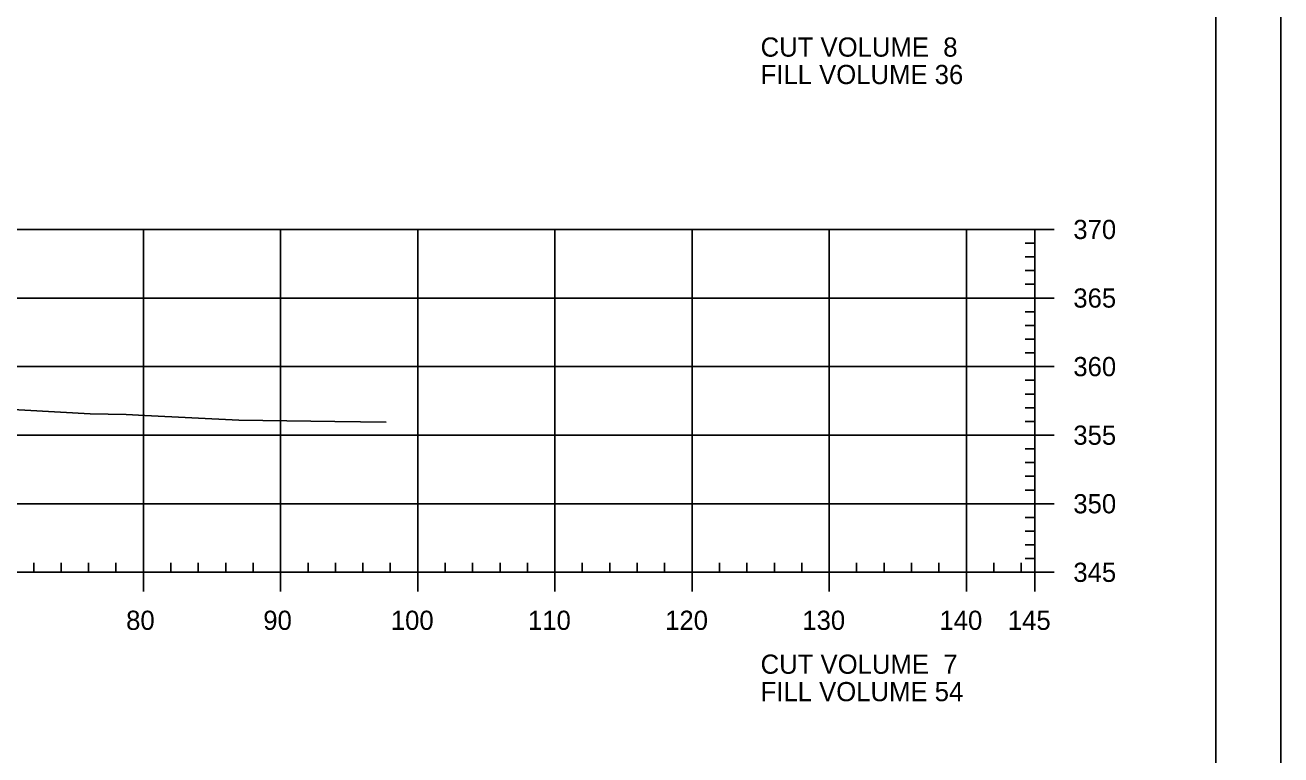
# Model space of a CAD drawing. Extents: x 1359801 to 1362404, y 372415 to 374228.
# Drawn here: x 1360042.7 to 1360134.3, y 373054.6 to 373107.8 of the extents above; entities that cross this region are included whole.
import ezdxf

# ---------------------------------------------------------------- set-up
doc = ezdxf.new("R2010")
doc.units = 0
for name, color, linetype in [('S_DRG_PT_SYM', 7, 'Continuous'), ('S_MAILBOX', 7, 'Continuous'), ('S_PRIMARY_CTL', 7, 'Continuous'), ('S_SHOULDER', 7, 'Continuous'), ('S_UTL_PT_SYM', 7, 'Continuous'), ('S_WATER_UTILITIES', 7, 'Continuous')]:
    doc.layers.add(name, color=color, linetype=linetype)

msp = doc.modelspace()

# ---------------------------------------------------------------- linework, layer by layer
at = {"layer": 'S_DRG_PT_SYM'}
msp.add_lwpolyline([(1360034.888, 373080.172), (1360047.473, 373079.465), (1360050.094, 373079.434), (1360051.445, 373079.352), (1360058.295, 373079.018), (1360065.315, 373078.917), (1360069.058, 373078.872)], dxfattribs=at)
at = {"layer": 'S_MAILBOX'}
for p, q in [((1359826.35, 373092.922), (1360116.35, 373092.922)), ((1360051.35, 373067.922), (1360051.35, 373092.922)), ((1360061.35, 373067.922), (1360061.35, 373092.922)), ((1360071.35, 373067.922), (1360071.35, 373092.922)), ((1360081.35, 373067.922), (1360081.35, 373092.922)), ((1360091.35, 373067.922), (1360091.35, 373092.922)), ((1360101.35, 373067.922), (1360101.35, 373092.922)), ((1360111.35, 373067.922), (1360111.35, 373092.922)), ((1360116.35, 373067.922), (1360116.35, 373092.922)), ((1359826.35, 373087.922), (1360116.35, 373087.922)), ((1359826.35, 373082.922), (1360116.35, 373082.922)), ((1359826.35, 373077.922), (1360116.35, 373077.922)), ((1359826.35, 373072.922), (1360116.35, 373072.922)), ((1359826.35, 373067.922), (1360116.35, 373067.922))]:
    msp.add_line(p, q, dxfattribs=at)
at = {"layer": 'S_SHOULDER'}
for points in [[(1359800.943, 373161.276), (1360134.283, 373161.276), (1360134.283, 372947.939), (1359800.943, 372947.939)], [(1360047.27, 373157.382), (1360047.27, 373147.502), (1360083.002, 373147.502), (1360083.002, 373144.582), (1360106.202, 373144.582), (1360106.202, 373120.249), (1360129.53, 373120.249), (1360129.53, 372951.922), (1359813.35, 372951.922), (1359813.35, 373157.382)]]:
    msp.add_lwpolyline(points, close=True, dxfattribs=at)
at = {"layer": 'S_UTL_PT_SYM'}
msp.add_line((1360129.53, 372951.922), (1360129.53, 373157.382), dxfattribs=at)
at = {"layer": 'S_WATER_UTILITIES'}
for p, q in [((1360116.35, 373067.922), (1360116.35, 373092.922)), ((1360117.75, 373092.922), (1360116.35, 373092.922)), ((1360116.35, 373091.922), (1360115.65, 373091.922)), ((1360116.35, 373090.922), (1360115.65, 373090.922)), ((1360116.35, 373089.922), (1360115.65, 373089.922)), ((1360116.35, 373088.922), (1360115.65, 373088.922)), ((1360117.75, 373087.922), (1360116.35, 373087.922)), ((1360116.35, 373086.922), (1360115.65, 373086.922)), ((1360116.35, 373085.922), (1360115.65, 373085.922)), ((1360116.35, 373084.922), (1360115.65, 373084.922)), ((1360116.35, 373083.922), (1360115.65, 373083.922)), ((1360117.75, 373082.922), (1360116.35, 373082.922)), ((1360116.35, 373081.922), (1360115.65, 373081.922)), ((1360116.35, 373080.922), (1360115.65, 373080.922)), ((1360116.35, 373079.922), (1360115.65, 373079.922)), ((1360116.35, 373078.922), (1360115.65, 373078.922)), ((1360117.75, 373077.922), (1360116.35, 373077.922)), ((1360116.35, 373076.922), (1360115.65, 373076.922)), ((1360116.35, 373075.922), (1360115.65, 373075.922)), ((1360116.35, 373074.922), (1360115.65, 373074.922)), ((1360116.35, 373073.922), (1360115.65, 373073.922)), ((1360117.75, 373072.922), (1360116.35, 373072.922)), ((1360116.35, 373071.922), (1360115.65, 373071.922)), ((1360116.35, 373070.922), (1360115.65, 373070.922)), ((1360116.35, 373069.922), (1360115.65, 373069.922)), ((1360043.35, 373067.922), (1360043.35, 373068.622)), ((1360045.35, 373067.922), (1360045.35, 373068.622)), ((1360047.35, 373067.922), (1360047.35, 373068.622)), ((1360049.35, 373067.922), (1360049.35, 373068.622)), ((1360053.35, 373067.922), (1360053.35, 373068.622)), ((1360055.35, 373067.922), (1360055.35, 373068.622)), ((1360057.35, 373067.922), (1360057.35, 373068.622)), ((1360059.35, 373067.922), (1360059.35, 373068.622)), ((1360063.35, 373067.922), (1360063.35, 373068.622)), ((1360065.35, 373067.922), (1360065.35, 373068.622)), ((1360067.35, 373067.922), (1360067.35, 373068.622)), ((1360069.35, 373067.922), (1360069.35, 373068.622)), ((1360073.35, 373067.922), (1360073.35, 373068.622)), ((1360075.35, 373067.922), (1360075.35, 373068.622)), ((1360077.35, 373067.922), (1360077.35, 373068.622)), ((1360079.35, 373067.922), (1360079.35, 373068.622)), ((1360083.35, 373067.922), (1360083.35, 373068.622)), ((1360085.35, 373067.922), (1360085.35, 373068.622)), ((1360087.35, 373067.922), (1360087.35, 373068.622)), ((1360089.35, 373067.922), (1360089.35, 373068.622)), ((1360093.35, 373067.922), (1360093.35, 373068.622)), ((1360095.35, 373067.922), (1360095.35, 373068.622)), ((1360097.35, 373067.922), (1360097.35, 373068.622)), ((1360099.35, 373067.922), (1360099.35, 373068.622)), ((1360103.35, 373067.922), (1360103.35, 373068.622)), ((1360105.35, 373067.922), (1360105.35, 373068.622)), ((1360107.35, 373067.922), (1360107.35, 373068.622)), ((1360109.35, 373067.922), (1360109.35, 373068.622)), ((1360113.35, 373067.922), (1360113.35, 373068.622)), ((1360115.35, 373067.922), (1360115.35, 373068.622)), ((1360116.35, 373068.922), (1360115.65, 373068.922)), ((1359826.35, 373067.922), (1360116.35, 373067.922)), ((1360051.35, 373066.522), (1360051.35, 373067.922)), ((1360061.35, 373066.522), (1360061.35, 373067.922)), ((1360071.35, 373066.522), (1360071.35, 373067.922)), ((1360081.35, 373066.522), (1360081.35, 373067.922)), ((1360091.35, 373066.522), (1360091.35, 373067.922)), ((1360101.35, 373066.522), (1360101.35, 373067.922)), ((1360111.35, 373066.522), (1360111.35, 373067.922)), ((1360116.35, 373066.522), (1360116.35, 373067.922)), ((1360117.75, 373067.922), (1360116.35, 373067.922))]:
    msp.add_line(p, q, dxfattribs=at)

# ---------------------------------------------------------------- texts
at = {"layer": 'S_PRIMARY_CTL'}
for s, p in [('CUT VOLUME  8', (1360096.35, 373105.522)), ('FILL VOLUME 36', (1360096.35, 373103.522)), ('370', (1360119.15, 373092.222)), ('365', (1360119.15, 373087.222)), ('360', (1360119.15, 373082.222)), ('355', (1360119.15, 373077.222)), ('350', (1360119.15, 373072.222)), ('345', (1360119.15, 373067.222)), ('80', (1360050.089, 373063.722)), ('90', (1360060.089, 373063.722)), ('100', (1360069.389, 373063.722)), ('110', (1360079.389, 373063.722)), ('120', (1360089.389, 373063.722)), ('130', (1360099.389, 373063.722)), ('140', (1360109.389, 373063.722)), ('145', (1360114.376, 373063.722)), ('CUT VOLUME  7', (1360096.35, 373060.522)), ('FILL VOLUME 54', (1360096.35, 373058.522))]:
    msp.add_text(s, height=1.4, dxfattribs=at).set_placement(p)

doc.saveas('drawing.dxf')
